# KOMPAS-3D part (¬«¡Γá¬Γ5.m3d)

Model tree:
1. Эскиз:1
2. Операция выдавливания:1
     Расстояние 1 = 8; Расстояние 2 = 8
3. Эскиз:2
4. Операция выдавливания:2
     Расстояние 1 = 0.5; Расстояние 2 = 8
5. Скругление:1
     Радиус = 0.3
6. Эскиз:3
7. Операция выдавливания:3
     Расстояние 1 = 0.5; Расстояние 2 = 8
8. Скругление:2
     Радиус = 0.3
9. Эскиз:4
10. Операция выдавливания:4
     Расстояние 1 = 0.5; Расстояние 2 = 6
11. Эскиз:5
12. Вырезать элемент выдавливания:1
     Расстояние 2 = 40; Расстояние 1 = 20
13. Скругление:3
     Радиус = 1.5
14. Эскиз:6
15. Операция выдавливания:5
     Расстояние 1 = 3; Расстояние 2 = 6
16. Эскиз:7
17. Операция выдавливания:6
     Расстояние 1 = 0.1; Расстояние 2 = 2
18. Эскиз:8
19. Операция выдавливания:7
     Расстояние 1 = 0.7; Расстояние 2 = 2
20. Скругление:5
     Радиус = 0.2
21. Скругление:6
     Радиус = 1
22. Эскиз:9
23. Операция выдавливания:8
     Расстояние 1 = 3; Расстояние 2 = 4
24. Скругление:7
     Радиус = 0.3

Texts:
  контакт5
  stalker61
  Сплав АЛ8  ГОСТ 1583-93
